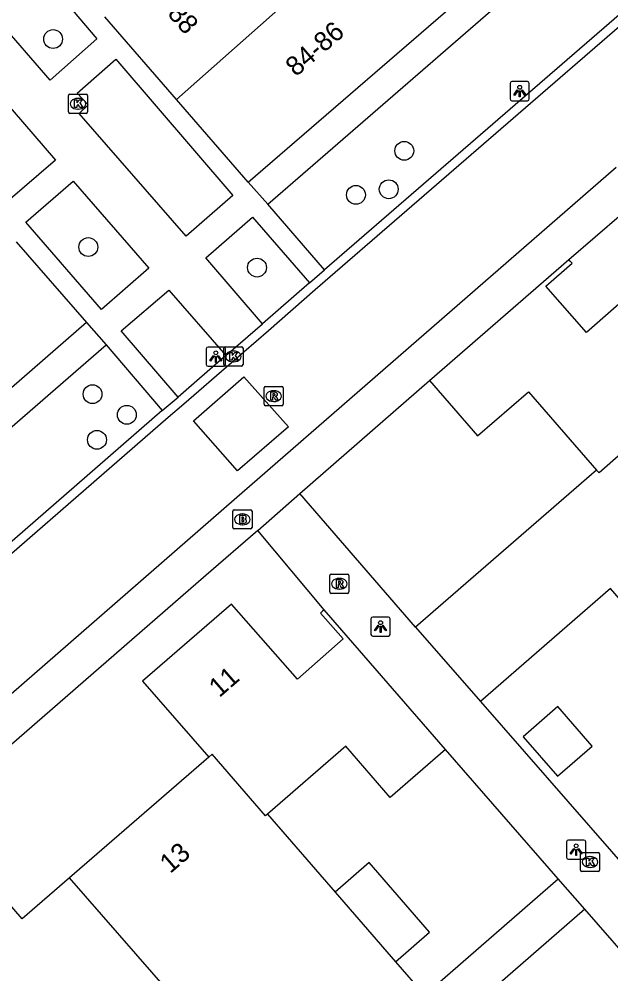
# Model space of a CAD drawing. Extents: x 155888 to 156864, y 383882 to 384671.
# Drawn here: x 156584.64 to 156615.36, y 384256.81 to 384306.4 of the extents above; entities that cross this region are included whole.
import ezdxf

# ---------------------------------------------------------------- set-up
doc = ezdxf.new("R2010")
doc.units = 0
for name, color, linetype in [('IMGEO_Boom', 7, 'Continuous'), ('IMGEO_Brandkraan', 7, 'Continuous'), ('IMGEO_Kolk', 7, 'Continuous'), ('IMGEO_Lichtpunt', 7, 'Continuous'), ('IMGEO_Muur', 7, 'Continuous'), ('IMGEO_Pand', 7, 'Continuous'), ('IMGEO_Pand_nummerreeks', 7, 'Continuous'), ('IMGEO_Rijbaan_lokaal_gesloten', 7, 'Continuous'), ('IMGEO_Rijbaan_lokaal_open', 7, 'Continuous'), ('IMGEO_Rioolput', 7, 'Continuous'), ('IMGEO_Voetpad_open', 7, 'Continuous')]:
    doc.layers.add(name, color=color, linetype=linetype)

msp = doc.modelspace()

# ---------------------------------------------------------------- linework, layer by layer
at = {"layer": 'IMGEO_Boom'}
for centre in [(156586.403, 384305.365), (156604.637, 384299.559), (156603.83, 384297.562), (156602.128, 384297.272), (156588.232, 384294.563), (156596.99, 384293.496), (156588.452, 384286.923), (156590.233, 384285.85), (156588.682, 384284.549)]:
    msp.add_circle(centre, 0.489, dxfattribs=at)
at = {"layer": 'IMGEO_Brandkraan'}
for p, q in [((156595.73, 384279.994), (156595.73, 384280.846)), ((156595.805, 384280.92), (156596.657, 384280.92)), ((156596.218, 384280.7), (156596.243, 384280.7)), ((156596.731, 384280.846), (156596.731, 384279.994)), ((156596.657, 384279.92), (156595.805, 384279.92)), ((156596.241, 384280.14), (156596.216, 384280.14))]:
    msp.add_line(p, q, dxfattribs=at)
for points in [[(156595.73, 384279.994), (156595.73, 384280.846)], [(156595.805, 384280.92), (156596.657, 384280.92)], [(156596.731, 384280.846), (156596.731, 384279.994)], [(156596.078, 384280.62), (156596.078, 384280.22), (156596.291, 384280.22)], [(156596.309, 384280.62), (156596.078, 384280.62)], [(156596.257, 384280.539), (156596.203, 384280.539), (156596.203, 384280.463)], [(156596.203, 384280.463), (156596.256, 384280.463)], [(156596.265, 384280.387), (156596.203, 384280.387), (156596.203, 384280.306)], [(156596.203, 384280.306), (156596.265, 384280.306)], [(156596.657, 384279.92), (156595.805, 384279.92)]]:
    msp.add_lwpolyline(points, dxfattribs=at)
for centre, radius, start, end in [((156595.807, 384280.844), 0.0765, 91.552, 178.448), ((156595.807, 384280.844), 0.0765, 91.552, 178.448), ((156596.655, 384280.844), 0.0765, 1.552, 88.448), ((156596.655, 384280.844), 0.0765, 1.552, 88.448), ((156596.258, 384280.501), 0.0379, 267.8285, 90.9355), ((156596.266, 384280.346), 0.0404, 269.8759, 90.5077), ((156596.297, 384280.471), 0.251, 268.6676, 293.5347), ((156596.313, 384280.475), 0.145, 59.4692, 91.5367), ((156596.338, 384280.522), 0.0922, 285.5137, 58.1501), ((156596.343, 384280.33), 0.105, 301.3115, 78.989), ((156595.807, 384279.996), 0.0765, 181.552, 268.448), ((156595.807, 384279.996), 0.0765, 181.552, 268.448), ((156596.655, 384279.996), 0.0765, 271.552, 358.448), ((156596.655, 384279.996), 0.0765, 271.552, 358.448)]:
    msp.add_arc(centre, radius, start, end, dxfattribs=at)
for centre, major_axis, ratio, start_param, end_param in [((156596.217, 384280.42), (-0.387, 0.002), 0.722429, 4.712389, 7.853982), ((156596.242, 384280.42), (-0.39, 0.002), 0.717154, 1.570796, 4.712389)]:
    msp.add_ellipse(centre, major_axis=major_axis, ratio=ratio, start_param=start_param, end_param=end_param, dxfattribs=at)
at = {"layer": 'IMGEO_Kolk'}
for p, q in [((156587.196, 384301.578), (156587.196, 384302.43)), ((156587.271, 384302.504), (156588.123, 384302.504)), ((156587.684, 384302.284), (156587.709, 384302.284)), ((156588.197, 384302.43), (156588.197, 384301.578)), ((156587.707, 384301.724), (156587.682, 384301.724)), ((156588.123, 384301.504), (156587.271, 384301.504)), ((156595.263, 384288.458), (156595.263, 384289.31)), ((156595.338, 384289.384), (156596.19, 384289.384)), ((156595.751, 384289.164), (156595.776, 384289.164)), ((156596.264, 384289.31), (156596.264, 384288.458)), ((156596.19, 384288.384), (156595.338, 384288.384)), ((156595.774, 384288.604), (156595.749, 384288.604)), ((156613.779, 384262.198), (156613.779, 384263.05)), ((156613.854, 384263.124), (156614.706, 384263.124)), ((156614.267, 384262.904), (156614.292, 384262.904)), ((156614.78, 384263.05), (156614.78, 384262.198)), ((156614.29, 384262.344), (156614.265, 384262.344)), ((156614.706, 384262.124), (156613.854, 384262.124))]:
    msp.add_line(p, q, dxfattribs=at)
for points in [[(156587.196, 384301.578), (156587.196, 384302.43)], [(156587.271, 384302.504), (156588.123, 384302.504)], [(156587.517, 384302.204), (156587.64, 384302.204), (156587.64, 384302.053), (156587.77, 384302.204), (156587.934, 384302.204), (156587.788, 384302.053), (156587.941, 384301.804), (156587.789, 384301.804), (156587.704, 384301.968), (156587.64, 384301.901), (156587.64, 384301.804), (156587.517, 384301.804), (156587.517, 384302.204)], [(156588.197, 384302.43), (156588.197, 384301.578)], [(156588.123, 384301.504), (156587.271, 384301.504)], [(156595.263, 384288.458), (156595.263, 384289.31)], [(156595.338, 384289.384), (156596.19, 384289.384)], [(156596.264, 384289.31), (156596.264, 384288.458)], [(156595.584, 384289.084), (156595.707, 384289.084), (156595.707, 384288.933), (156595.837, 384289.084), (156596.001, 384289.084), (156595.855, 384288.933), (156596.008, 384288.684), (156595.856, 384288.684), (156595.771, 384288.848), (156595.707, 384288.781), (156595.707, 384288.684), (156595.584, 384288.684), (156595.584, 384289.084)], [(156596.19, 384288.384), (156595.338, 384288.384)], [(156613.779, 384262.198), (156613.779, 384263.05)], [(156613.854, 384263.124), (156614.706, 384263.124)], [(156614.78, 384263.05), (156614.78, 384262.198)], [(156614.1, 384262.824), (156614.223, 384262.824), (156614.223, 384262.673), (156614.353, 384262.824), (156614.517, 384262.824), (156614.371, 384262.673), (156614.524, 384262.424), (156614.372, 384262.424), (156614.287, 384262.588), (156614.223, 384262.521), (156614.223, 384262.424), (156614.1, 384262.424), (156614.1, 384262.824)], [(156614.706, 384262.124), (156613.854, 384262.124)]]:
    msp.add_lwpolyline(points, dxfattribs=at)
for centre, start, end in [((156587.273, 384302.428), 91.552, 178.448), ((156587.273, 384302.428), 91.552, 178.448), ((156588.121, 384302.428), 1.552, 88.448), ((156588.121, 384302.428), 1.552, 88.448), ((156587.273, 384301.58), 181.552, 268.448), ((156587.273, 384301.58), 181.552, 268.448), ((156588.121, 384301.58), 271.552, 358.448), ((156588.121, 384301.58), 271.552, 358.448), ((156595.34, 384289.308), 91.552, 178.448), ((156595.34, 384289.308), 91.552, 178.448), ((156596.188, 384289.308), 1.552, 88.448), ((156596.188, 384289.308), 1.552, 88.448), ((156595.34, 384288.46), 181.552, 268.448), ((156595.34, 384288.46), 181.552, 268.448), ((156596.188, 384288.46), 271.552, 358.448), ((156596.188, 384288.46), 271.552, 358.448), ((156613.856, 384263.048), 91.552, 178.448), ((156613.856, 384263.048), 91.552, 178.448), ((156614.704, 384263.048), 1.552, 88.448), ((156614.704, 384263.048), 1.552, 88.448), ((156613.856, 384262.2), 181.552, 268.448), ((156613.856, 384262.2), 181.552, 268.448), ((156614.704, 384262.2), 271.552, 358.448), ((156614.704, 384262.2), 271.552, 358.448)]:
    msp.add_arc(centre, 0.0765, start, end, dxfattribs=at)
for centre, major_axis, ratio, start_param, end_param in [((156587.683, 384302.004), (-0.387, 0.002), 0.722429, 4.712389, 7.853982), ((156587.708, 384302.004), (-0.39, 0.002), 0.717154, 1.570796, 4.712389), ((156595.75, 384288.884), (-0.387, 0.002), 0.722429, 4.712389, 7.853982), ((156595.775, 384288.884), (-0.39, 0.002), 0.717154, 1.570796, 4.712389), ((156614.266, 384262.624), (-0.387, 0.002), 0.722429, 4.712389, 7.853982), ((156614.291, 384262.624), (-0.39, 0.002), 0.717154, 1.570796, 4.712389)]:
    msp.add_ellipse(centre, major_axis=major_axis, ratio=ratio, start_param=start_param, end_param=end_param, dxfattribs=at)
at = {"layer": 'IMGEO_Lichtpunt'}
for p, q in [((156610.131, 384303.063), (156610.131, 384302.256)), ((156610.131, 384303.063), (156610.131, 384302.256)), ((156611.033, 384303.158), (156610.225, 384303.158)), ((156611.033, 384303.158), (156610.225, 384303.158)), ((156611.127, 384302.256), (156611.127, 384303.063)), ((156611.127, 384302.256), (156611.127, 384303.063)), ((156610.225, 384302.162), (156611.033, 384302.162)), ((156610.225, 384302.162), (156611.033, 384302.162)), ((156594.353, 384289.27), (156594.353, 384288.463)), ((156594.353, 384289.27), (156594.353, 384288.463)), ((156595.255, 384289.365), (156594.447, 384289.365)), ((156595.255, 384289.365), (156594.447, 384289.365)), ((156595.349, 384288.463), (156595.349, 384289.27)), ((156595.349, 384288.463), (156595.349, 384289.27)), ((156594.447, 384288.369), (156595.255, 384288.369)), ((156594.447, 384288.369), (156595.255, 384288.369)), ((156602.907, 384275.253), (156602.907, 384274.446)), ((156602.907, 384275.253), (156602.907, 384274.446)), ((156603.809, 384275.348), (156603.001, 384275.348)), ((156603.809, 384275.348), (156603.001, 384275.348)), ((156603.903, 384274.446), (156603.903, 384275.253)), ((156603.903, 384274.446), (156603.903, 384275.253)), ((156603.001, 384274.352), (156603.809, 384274.352)), ((156603.001, 384274.352), (156603.809, 384274.352)), ((156613.062, 384263.665), (156613.062, 384262.858)), ((156613.062, 384263.665), (156613.062, 384262.858)), ((156613.964, 384263.76), (156613.156, 384263.76)), ((156613.964, 384263.76), (156613.156, 384263.76)), ((156614.058, 384262.858), (156614.058, 384263.665)), ((156614.058, 384262.858), (156614.058, 384263.665)), ((156613.156, 384262.764), (156613.964, 384262.764)), ((156613.156, 384262.764), (156613.964, 384262.764))]:
    msp.add_line(p, q, dxfattribs=at)
for points in [[(156610.505, 384302.727), (156610.544, 384302.699), (156610.356, 384302.437), (156610.318, 384302.464), (156610.505, 384302.727)], [(156610.607, 384302.679), (156610.654, 384302.679), (156610.654, 384302.357), (156610.607, 384302.357), (156610.607, 384302.679)], [(156610.717, 384302.699), (156610.755, 384302.726), (156610.942, 384302.464), (156610.903, 384302.436), (156610.717, 384302.699)], [(156594.727, 384288.934), (156594.766, 384288.906), (156594.578, 384288.644), (156594.54, 384288.671), (156594.727, 384288.934)], [(156594.829, 384288.886), (156594.876, 384288.886), (156594.876, 384288.564), (156594.829, 384288.564), (156594.829, 384288.886)], [(156594.939, 384288.906), (156594.977, 384288.933), (156595.164, 384288.671), (156595.125, 384288.643), (156594.939, 384288.906)], [(156603.281, 384274.917), (156603.32, 384274.889), (156603.132, 384274.627), (156603.094, 384274.654), (156603.281, 384274.917)], [(156603.383, 384274.869), (156603.43, 384274.869), (156603.43, 384274.547), (156603.383, 384274.547), (156603.383, 384274.869)], [(156603.493, 384274.889), (156603.531, 384274.916), (156603.718, 384274.654), (156603.679, 384274.626), (156603.493, 384274.889)], [(156613.436, 384263.329), (156613.475, 384263.301), (156613.287, 384263.039), (156613.249, 384263.066), (156613.436, 384263.329)], [(156613.538, 384263.281), (156613.585, 384263.281), (156613.585, 384262.959), (156613.538, 384262.959), (156613.538, 384263.281)], [(156613.648, 384263.301), (156613.686, 384263.328), (156613.873, 384263.066), (156613.834, 384263.038), (156613.648, 384263.301)]]:
    msp.add_lwpolyline(points, dxfattribs=at)
for centre in [(156610.63, 384302.861), (156594.852, 384289.068), (156603.406, 384275.051), (156613.561, 384263.463)]:
    msp.add_circle(centre, 0.0994, dxfattribs=at)
for centre, start, end in [((156610.225, 384303.063), 90, 180), ((156610.225, 384303.063), 90, 180), ((156611.033, 384303.063), 0, 90), ((156611.033, 384303.063), 0, 90), ((156610.225, 384302.256), 180, 270), ((156610.225, 384302.256), 180, 270), ((156611.033, 384302.256), 270, 0), ((156611.033, 384302.256), 270, 360), ((156594.447, 384289.27), 90, 180), ((156594.447, 384289.27), 90, 180), ((156595.255, 384289.27), 0, 90), ((156595.255, 384289.27), 0, 90), ((156594.447, 384288.463), 180, 270), ((156594.447, 384288.463), 180, 270), ((156595.255, 384288.463), 270, 0), ((156595.255, 384288.463), 270, 360), ((156603.001, 384275.253), 90, 180), ((156603.001, 384275.253), 90, 180), ((156603.809, 384275.253), 0, 90), ((156603.809, 384275.253), 0, 90), ((156603.001, 384274.446), 180, 270), ((156603.001, 384274.446), 180, 270), ((156603.809, 384274.446), 270, 0), ((156603.809, 384274.446), 270, 360), ((156613.156, 384263.665), 90, 180), ((156613.156, 384263.665), 90, 180), ((156613.964, 384263.665), 0, 90), ((156613.964, 384263.665), 0, 90), ((156613.156, 384262.858), 180, 270), ((156613.156, 384262.858), 180, 270), ((156613.964, 384262.858), 270, 0), ((156613.964, 384262.858), 270, 360)]:
    msp.add_arc(centre, 0.0946, start, end, dxfattribs=at)
at = {"layer": 'IMGEO_Muur'}
for points in [[(156599.212, 384281.758), (156605.946, 384287.631)], [(156605.227, 384274.827), (156599.212, 384281.758)]]:
    msp.add_lwpolyline(points, dxfattribs=at)
at = {"layer": 'IMGEO_Pand'}
for points in [[(156600.181, 384308.765), (156592.809, 384302.231)], [(156596.536, 384297.941), (156608.799, 384308.553)], [(156592.809, 384302.231), (156589.086, 384306.515)], [(156596.536, 384297.941), (156592.809, 384302.231)], [(156584.49, 384294.84), (156588.136, 384290.64)], [(156605.946, 384287.631), (156613.173, 384293.923)], [(156618.096, 384285.553), (156622.028, 384288.967), (156618.021, 384293.565), (156614.096, 384290.127), (156611.994, 384292.538), (156613.35, 384293.72), (156613.248, 384293.837), (156613.173, 384293.923)], [(156588.136, 384290.64), (156575.908, 384279.994)], [(156605.946, 384287.631), (156608.441, 384284.759), (156611.083, 384287.051), (156614.62, 384282.974)], [(156618.096, 384285.553), (156617.984, 384285.681), (156614.747, 384282.828), (156614.62, 384282.974)], [(156614.62, 384282.974), (156605.227, 384274.827)], [(156618.494, 384273.201), (156615.342, 384276.828), (156608.6, 384270.968)], [(156600.482, 384275.728), (156600.398, 384275.654), (156600.281, 384275.551), (156601.46, 384274.208), (156599.087, 384272.125), (156595.658, 384276.02), (156591.046, 384272.012), (156594.481, 384268.066)], [(156606.777, 384268.466), (156600.482, 384275.728)], [(156605.227, 384274.827), (156608.6, 384270.968)], [(156612.588, 384267.076), (156614.389, 384268.641), (156612.606, 384270.692), (156610.806, 384269.127), (156612.588, 384267.076)], [(156606.777, 384268.466), (156603.909, 384265.98), (156601.607, 384268.637), (156597.539, 384265.111)], [(156594.481, 384268.066), (156592.028, 384265.938), (156587.252, 384261.796)], [(156597.539, 384265.111), (156597.433, 384265.019), (156594.66, 384268.221), (156594.481, 384268.066)], [(156597.539, 384265.111), (156601.047, 384261.064)], [(156587.252, 384261.796), (156584.804, 384259.673), (156581.396, 384263.602), (156576.801, 384259.602), (156580.226, 384255.714)], [(156604.182, 384257.447), (156605.951, 384258.98), (156602.816, 384262.597), (156601.047, 384261.064)], [(156591.877, 384255.525), (156592.367, 384255.953), (156587.252, 384261.796)], [(156601.047, 384261.064), (156604.182, 384257.447)], [(156604.182, 384257.447), (156605.689, 384255.708)]]:
    msp.add_lwpolyline(points, dxfattribs=at)
at = {"layer": 'IMGEO_Rijbaan_lokaal_gesloten'}
for points in [[(156571.738, 384267.772), (156592.371, 384285.726), (156593.191, 384286.413), (156595.67, 384288.575), (156597.58, 384290.233), (156600.011, 384292.356), (156600.79, 384293.039), (156618.252, 384308.162), (156618.352, 384308.234), (156621.528, 384310.997), (156639.159, 384326.393), (156639.947, 384327.044), (156642.471, 384329.247), (156644.425, 384330.963), (156646.82, 384333.008)], [(156557.467, 384248.05), (156559.705, 384250), (156595.803, 384281.453), (156615.646, 384298.718)]]:
    msp.add_lwpolyline(points, dxfattribs=at)
at = {"layer": 'IMGEO_Rijbaan_lokaal_open'}
for points in [[(156617.967, 384308.524), (156600.488, 384293.386)], [(156599.708, 384292.702), (156600.488, 384293.386)], [(156599.708, 384292.702), (156597.278, 384290.58)], [(156595.368, 384288.922), (156597.278, 384290.58)], [(156595.368, 384288.922), (156592.893, 384286.763)], [(156598.62, 384285.221), (156595.976, 384282.935), (156593.688, 384285.544), (156596.312, 384287.822), (156598.62, 384285.221)], [(156592.072, 384286.076), (156592.893, 384286.763)], [(156592.072, 384286.076), (156574.465, 384270.754)]]:
    msp.add_lwpolyline(points, dxfattribs=at)
at = {"layer": 'IMGEO_Rioolput'}
for p, q in [((156597.355, 384286.394), (156597.355, 384287.246)), ((156597.43, 384287.32), (156598.282, 384287.32)), ((156598.356, 384287.246), (156598.356, 384286.394)), ((156597.843, 384287.1), (156597.868, 384287.1)), ((156598.282, 384286.32), (156597.43, 384286.32)), ((156597.866, 384286.54), (156597.841, 384286.54)), ((156600.765, 384276.648), (156600.765, 384277.5)), ((156600.84, 384277.574), (156601.692, 384277.574)), ((156601.253, 384277.354), (156601.278, 384277.354)), ((156601.766, 384277.5), (156601.766, 384276.648)), ((156601.276, 384276.794), (156601.251, 384276.794)), ((156601.692, 384276.574), (156600.84, 384276.574))]:
    msp.add_line(p, q, dxfattribs=at)
for points in [[(156597.355, 384286.394), (156597.355, 384287.246)], [(156597.43, 384287.32), (156598.282, 384287.32)], [(156598.356, 384287.246), (156598.356, 384286.394)], [(156597.944, 384287.018), (156597.692, 384287.02), (156597.692, 384286.62)], [(156597.692, 384286.62), (156597.816, 384286.62), (156597.816, 384286.782), (156597.827, 384286.782)], [(156597.87, 384286.939), (156597.816, 384286.939), (156597.816, 384286.858)], [(156597.816, 384286.858), (156597.868, 384286.858)], [(156597.874, 384286.753), (156597.945, 384286.62), (156598.085, 384286.62), (156598.02, 384286.746)], [(156598.282, 384286.32), (156597.43, 384286.32)], [(156600.765, 384276.648), (156600.765, 384277.5)], [(156600.84, 384277.574), (156601.692, 384277.574)], [(156601.354, 384277.272), (156601.102, 384277.274), (156601.102, 384276.874)], [(156601.766, 384277.5), (156601.766, 384276.648)], [(156601.102, 384276.874), (156601.226, 384276.874), (156601.226, 384277.036), (156601.237, 384277.036)], [(156601.28, 384277.193), (156601.226, 384277.193), (156601.226, 384277.112)], [(156601.226, 384277.112), (156601.278, 384277.112)], [(156601.284, 384277.007), (156601.355, 384276.874), (156601.495, 384276.874), (156601.43, 384277)], [(156601.692, 384276.574), (156600.84, 384276.574)]]:
    msp.add_lwpolyline(points, dxfattribs=at)
for centre, radius, start, end in [((156597.432, 384287.244), 0.0765, 91.552, 178.448), ((156597.432, 384287.244), 0.0765, 91.552, 178.448), ((156598.28, 384287.244), 0.0765, 1.552, 88.448), ((156598.28, 384287.244), 0.0765, 1.552, 88.448), ((156597.826, 384286.729), 0.0533, 26.0293, 88.6989), ((156597.852, 384287.047), 0.19, 274.7715, 282.9687), ((156597.876, 384286.843), 0.0964, 77.0061, 93.1865), ((156597.89, 384286.9), 0.0378, 276.6634, 79.6772), ((156597.943, 384286.908), 0.109, 350.3612, 89.416), ((156597.941, 384286.908), 0.112, 277.5842, 350.9817), ((156597.925, 384286.693), 0.108, 29.5134, 73.7905), ((156597.432, 384286.396), 0.0765, 181.552, 268.448), ((156597.432, 384286.396), 0.0765, 181.552, 268.448), ((156598.28, 384286.396), 0.0765, 271.552, 358.448), ((156598.28, 384286.396), 0.0765, 271.552, 358.448), ((156600.842, 384277.498), 0.0765, 91.552, 178.448), ((156600.842, 384277.498), 0.0765, 91.552, 178.448), ((156601.353, 384277.162), 0.109, 350.3612, 89.416), ((156601.69, 384277.498), 0.0765, 1.552, 88.448), ((156601.69, 384277.498), 0.0765, 1.552, 88.448), ((156601.236, 384276.983), 0.0533, 26.0293, 88.6989), ((156601.262, 384277.301), 0.19, 274.7715, 282.9687), ((156601.286, 384277.097), 0.0964, 77.0061, 93.1865), ((156601.3, 384277.154), 0.0378, 276.6634, 79.6772), ((156601.351, 384277.162), 0.112, 277.5842, 350.9817), ((156601.335, 384276.947), 0.108, 29.5134, 73.7905), ((156600.842, 384276.65), 0.0765, 181.552, 268.448), ((156600.842, 384276.65), 0.0765, 181.552, 268.448), ((156601.69, 384276.65), 0.0765, 271.552, 358.448), ((156601.69, 384276.65), 0.0765, 271.552, 358.448)]:
    msp.add_arc(centre, radius, start, end, dxfattribs=at)
for centre, major_axis, ratio, start_param, end_param in [((156597.842, 384286.82), (-0.387, 0.002), 0.722429, 4.712389, 7.853982), ((156597.867, 384286.82), (-0.39, 0.002), 0.717154, 1.570796, 4.712389), ((156601.252, 384277.074), (-0.387, 0.002), 0.722429, 4.712389, 7.853982), ((156601.277, 384277.074), (-0.39, 0.002), 0.717154, 1.570796, 4.712389)]:
    msp.add_ellipse(centre, major_axis=major_axis, ratio=ratio, start_param=start_param, end_param=end_param, dxfattribs=at)
at = {"layer": 'IMGEO_Voetpad_open'}
for points in [[(156597.548, 384296.785), (156615.083, 384312.005)], [(156583.452, 384306.45), (156585.92, 384308.635), (156588.671, 384305.378), (156586.252, 384303.231), (156583.452, 384306.45)], [(156588.228, 384301.946), (156587.65, 384302.549), (156589.659, 384304.318), (156595.731, 384297.241), (156593.319, 384295.128), (156587.752, 384301.506), (156588.228, 384301.946)], [(156583.735, 384302.311), (156586.53, 384299.082), (156584.048, 384296.942), (156581.268, 384300.165), (156583.735, 384302.311)], [(156587.453, 384297.983), (156591.379, 384293.459), (156588.92, 384291.314), (156584.985, 384295.855), (156587.453, 384297.983)], [(156597.548, 384296.785), (156596.536, 384297.941)], [(156613.173, 384293.923), (156617.274, 384297.449)], [(156600.488, 384293.386), (156597.548, 384296.785)], [(156597.278, 384290.58), (156594.327, 384293.996), (156596.753, 384296.113), (156599.708, 384292.702)], [(156592.893, 384286.763), (156589.934, 384290.204), (156592.406, 384292.326), (156595.368, 384288.922)], [(156588.136, 384290.64), (156589.163, 384289.478)], [(156571.506, 384274.157), (156589.163, 384289.478)], [(156589.163, 384289.478), (156592.072, 384286.076)], [(156599.212, 384281.758), (156605.946, 384287.631)], [(156597.028, 384279.837), (156599.212, 384281.758)], [(156605.227, 384274.827), (156599.212, 384281.758)], [(156597.028, 384279.837), (156594.345, 384277.515), (156561.215, 384248.704), (156558.76, 384246.548)], [(156600.482, 384275.728), (156597.028, 384279.837)], [(156608.6, 384270.968), (156617.657, 384260.571)], [(156612.627, 384261.755), (156606.777, 384268.466)], [(156605.689, 384255.708), (156612.627, 384261.755)], [(156614.009, 384260.168), (156612.627, 384261.755)], [(156614.009, 384260.168), (156607.077, 384254.126)], [(156619.925, 384253.381), (156614.009, 384260.168)]]:
    msp.add_lwpolyline(points, dxfattribs=at)

# ---------------------------------------------------------------- texts
at = {"layer": 'IMGEO_Pand_nummerreeks'}
for s, rotation, p in [('88', 310.9855, (156592.299, 384306.661)), ('84-86', 40.7589, (156599.011, 384303.378)), ('11', 40.9919, (156595.034, 384271.133)), ('13', 40.9378, (156592.484, 384261.993))]:
    msp.add_text(s, height=1, rotation=rotation, dxfattribs=at).set_placement(p)

doc.saveas('drawing.dxf')
